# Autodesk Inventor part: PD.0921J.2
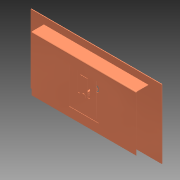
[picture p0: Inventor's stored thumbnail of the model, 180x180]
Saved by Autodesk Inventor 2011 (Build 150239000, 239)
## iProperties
Created: 2014-06
Part Number: PD.0921J.2
Document SubType Name: Modeling
Designer: Evgeny
Density: 1 g/cm^3
Author: Evgeny
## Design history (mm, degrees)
sketch "Эскиз1"
  geometry: L1 (-76, 40)-(76, 40); L2 (76, 40)-(76, -40); L3 (76, -40)-(-76, -40); L4 (-76, -40)-(-76, 40); L5 (21.65, 24.95)-(21.65, -26.8); L6 (21.65, -26.8)-(-21.65, -26.8); L7 (-21.65, -26.8)-(-21.65, 24.95); L8 (17.95, 24.95)-(17.95, -23.1); L9 (17.95, -23.1)-(-17.95, -23.1); L10 (-17.95, -23.1)-(-17.95, 24.95); L11 (-21.65, 24.95)-(-17.95, 24.95); L12 (17.95, 24.95)-(21.65, 24.95); L13 (-9, 24.95)-(9, 24.95); L14 (9, 24.95)-(9, -2.55); L15 (-9, -2.55)-(-9, 24.95); L16 (-5.3, -2.55)-(-5.3, 21.25); L17 (-5.3, 21.25)-(5.3, 21.25); L18 (5.3, 21.25)-(5.3, -2.55); L19 (9, -2.55)-(5.3, -2.55); L20 (-5.3, -2.55)-(-9, -2.55); C1 r 3 at (0, -2.7); 1 further point
  constraints: 40 end point, 10 parallel, 4 horizontal, 4 perpendicular, 3 collinear, 1 centre point
  dimensions: "d0" = 80 distance between parallel lines of L3 L1; "d1" = 152 distance between parallel lines of L2 L4; "d2" = 76 distance from line of L4 point (0, 0); "d4" = 3.7 distance between parallel lines of L10 L7; "d5" = 3.7 distance between parallel lines of L5 L8; "d6" = 3.7 distance between parallel lines of L6 L9; "d7" = 51.75 distance between parallel lines of L12 L6; "d9" = 43.3 distance between parallel lines of L5 L7; "d10" = 21.65 distance from line of L7 point (0, 0); "d11" = 3.7 distance between parallel lines of L16 L15; "d12" = 3.7 distance between parallel lines of L18 L14; "d13" = 3.7 distance between parallel lines of L13 L17; "d14" = 27.5 distance between parallel lines of L13 L20; "d15" = 18 distance between parallel lines of L14 L15; "d16" = 9 distance from line of point (0, 0) L15; "d19" = 6 diameter of C1; "d20" = 42.7 distance from line of L1 C1.centre; "d43" = 13.2 distance between parallel lines of L3 L6; "d50" = 40 distance from line of L1 point (0, 0)
extrude "Выдавливание2" new body sketch "Эскиз1" distance "d21" = 0.5; taper "d22" = 0 deg
extrude "Выдавливание3" join sketch "Эскиз1" distance "d23" = 1.5; taper "d25" = 0 deg; dims "d24" = 17.5, "d26" = 0
sketch "Эскиз2"
  geometry: L1 (76, -40)-(76, 40) reference; L2 (-76, 40)-(76, 40); L3 (76, 40)-(76, 39.5); L4 (76, 39.5)-(-76, 39.5); L5 (-76, 39.5)-(-76, 40); 1 further point
  constraints: 8 end point, 2 parallel, 1 horizontal, 1 perpendicular, 1 point on line
  dimensions: "d27" = 0.5 distance between parallel lines of L4 L2
extrude "Выдавливание4" join sketch "Эскиз2" distance "d28" = 17.5; taper "d29" = 0 deg
fillet "Сопряжение1" dims "d30" = 1.5
fillet "Сопряжение2" dims "d31" = 1
sketch "Эскиз3"
  geometry: L1 (-95, 50)-(95, 50); L2 (95, 50)-(95, -50); L3 (95, -50)-(-95, -50); L4 (-95, -50)-(-95, 50); C1 r 4.5 at (0, -2.7); 1 further point
  constraints: 8 end point, 2 parallel, 1 centre point, 1 horizontal, 1 perpendicular
  dimensions: "d34" = 100 distance between parallel lines of L3 L1; "d35" = 190 distance between parallel lines of L2 L4; "d44" = 95 distance from line of L4 point (0, 0); "d45" = 50 distance from line of L1 point (0, 0); "d46" = 9 diameter of C1; "d47" = 2.7 distance of C1.centre point (0, 0)
extrude "Выдавливание7" join sketch "Эскиз3" distance "d48" = 1; taper "d49" = 0 deg
node "Твердое тело2"
